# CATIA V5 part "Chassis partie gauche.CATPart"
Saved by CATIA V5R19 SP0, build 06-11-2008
Part number: Bati
Bounding box of the stored display mesh (mm): x 0 to 60, y 0 to 700, z 0 to 900
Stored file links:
  C:\Users\Hicham57\Desktop\Chassis presse\Chassis partie gauche.CATPart
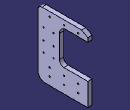
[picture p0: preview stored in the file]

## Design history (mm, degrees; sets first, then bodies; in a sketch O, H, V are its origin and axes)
Body1 (main body)
  Sketch1 on yz-plane, origin (0, 0, 0), H (0, 1, 0), V (0, 0, 1)
    line L1 (101.0295, 0) -> (700, 0)
    point P1 (700, 0)
    line L2 (700, 0) -> (700, 320)
    line L3 (700, 320) -> (365.2402, 320)
    line L4 (300, 385.2402) -> (300, 701.3231)
    line L5 (393.6769, 795) -> (700, 795)
    point P3 (700, 795)
    line L6 (700, 795) -> (700, 850)
    line L7 (700, 850) -> (613.3975, 900)
    line L8 (613.3975, 900) -> (58.246, 900)
    point P6 (0, 900)
    line L9 (0, 841.754) -> (0, 101.0295)
    arc A1 centre (365.2402, 385.2402) radius 65.2402 from (365.2402, 320) to (300, 385.2402) cw
    arc A2 centre (393.6769, 701.3231) radius 93.6769 from (300, 701.3231) to (393.6769, 795) cw
    arc A3 centre (58.246, 841.754) radius 58.246 from (58.246, 900) to (0, 841.754) ccw
    arc A4 centre (101.0295, 101.0295) radius 101.0295 from (101.0295, 0) to (0, 101.0295) cw
    length L2 = 320
    distance L3 L5 = 475
    distance L4 L9 = 300
    length L7 = 100
    angle L5 L7 = 150
    radius A1 = 65.2402
    radius A2 = 93.6769
    distance P6 O = 900
    radius A3 = 58.246
    distance O P1 = 700
    radius A4 = 101.0295
    horizontal: L1 H, L3 H, L5 H, L8 H
    vertical: L2 V, L4 V, L6 V, L9 V
    coincidence: P3 L2, P6 V, L8 P6, L9 P6, L1 O, L9 O
    tangency: A1 L3, A1 L4, A2 L4, A2 L5, A3 L8, A3 L9, A4 L1, A4 L9
  Pad1: profile Sketch1, direction (1, 0, 0), length 60
  Sketch2 on end face of Pad1, origin (60, 0, 0), H (0, 1, 0), V (0, 0, 1)
  Sketch3 on start face of Pad1, origin (0, 0, 0), H (0, -1, 0), V (0, 0, 1)
    line L1 (-655, 855) -> (-25, 855)
    line L2 (-25, 855) -> (-25, 815)
    line L3 (-25, 815) -> (-655, 815)
    line L4 (-655, 815) -> (-655, 855)
    line L5 (-275, 685) -> (-25, 685)
    line L6 (-25, 685) -> (-25, 645)
    line L7 (-25, 645) -> (-275, 645)
    line L8 (-275, 645) -> (-275, 685)
    point P7 (-25, 645)
    point P9 (-275, 525)
    line L9 (-275, 525) -> (-25, 525)
    line L10 (-25, 525) -> (-25, 485)
    line L11 (-25, 485) -> (-275, 485)
    line L12 (-275, 485) -> (-275, 525)
    point P11 (-25, 485)
    line L13 (-275, 380) -> (-25, 380)
    line L14 (-25, 380) -> (-25, 340)
    line L15 (-25, 340) -> (-275, 340)
    line L16 (-275, 340) -> (-275, 380)
    point P17 (-655, 240)
    line L17 (-655, 240) -> (-25, 240)
    line L18 (-25, 240) -> (-25, 200)
    line L19 (-25, 200) -> (-655, 200)
    line L20 (-655, 200) -> (-655, 240)
    point P19 (-25, 200)
    point P21 (-655, 130)
    line L21 (-655, 130) -> (-25, 130)
    line L22 (-25, 130) -> (-25, 90)
    line L23 (-25, 90) -> (-655, 90)
    line L24 (-655, 90) -> (-655, 130)
    point P23 (-25, 90)
    length L1 = 630
    length L2 = 40
    distance L3 H = 815
    length L8 = 40
    distance L11 L9 = 40
    distance L15 L13 = 40
    distance L6 L8 = 250
    length L15 = 250
    distance V L6 = 25
    distance L7 H = 645
    distance L11 H = 485
    distance L14 V = 25
    distance L15 H = 340
    distance L19 H = 200
    length L20 = 40
    length L24 = 40
    distance H L23 = 90
    horizontal: L1 H, L3 H, L5 H, L7 H, L9 H, L11 H, L13 H, L15 H, L17 H, L19 H, L21 H, L23 H
    vertical: L2 V, L4 V, L6 V, L8 V, L10 V, L12 V, L14 V, L16 V, L18 V, L20 V, L22 V, L24 V
    coincidence: P7 L2, P9 L8, P11 L2, P17 L4, P19 L14, P21 L4, P23 L2
  Pocket1: profile Sketch3, direction (1, 0, 0), length 30
  Sketch4 on end face of Pad1, origin (60, 0, 0), H (0, 1, 0), V (0, 0, 1)
    circle A1 centre (165, 835) radius 10
    point P1 (165, 835)
    circle A2 centre (565, 835) radius 10
    point P2 (565, 835)
    circle A3 centre (80, 665) radius 10
    point P3 (80, 665)
    circle A4 centre (220, 665) radius 10
    point P4 (220, 665)
    circle A5 centre (80, 505) radius 10
    point P5 (80, 505)
    circle A6 centre (220, 505) radius 10
    point P6 (220, 505)
    circle A7 centre (80, 360) radius 10
    point P7 (80, 360)
    circle A8 centre (220, 360) radius 10
    point P8 (220, 360)
    circle A9 centre (165, 220) radius 10
    point P9 (165, 220)
    circle A10 centre (365, 220) radius 10
    point P10 (365, 220)
    circle A11 centre (565, 220) radius 10
    point P11 (565, 220)
    circle A12 centre (165, 110) radius 10
    point P12 (165, 110)
    circle A13 centre (365, 110) radius 10
    point P13 (365, 110)
    circle A14 centre (565, 110) radius 10
    point P14 (565, 110)
    circle A15 centre (365, 835) radius 10
    point P15 (365, 835)
    reference projected line E1 (25, 815) -> (25, 855) from edge [end face of Pocket1 | face of Pocket1 from Sketch3.L2]
    reference projected line E2 (655, 815) -> (25, 815) from edge [end face of Pocket1 | face of Pocket1 from Sketch3.L3]
    reference projected line E3 (655, 815) -> (25, 815) from edge [end face of Pocket1 | face of Pocket1 from Sketch3.L3]
    reference projected line E4 (655, 815) -> (25, 815) from edge [end face of Pocket1 | face of Pocket1 from Sketch3.L3]
    reference projected line E5 (25, 200) -> (25, 240) from edge [start face of Pad1 | face of Pocket1 from Sketch3.L18]
    reference projected line E6 (655, 200) -> (25, 200) from edge [end face of Pocket1 | face of Pocket1 from Sketch3.L19]
    reference projected line E7 (655, 200) -> (25, 200) from edge [end face of Pocket1 | face of Pocket1 from Sketch3.L19]
    reference projected line E8 (655, 200) -> (25, 200) from edge [end face of Pocket1 | face of Pocket1 from Sketch3.L19]
    reference projected line E9 (25, 90) -> (25, 130) from edge [end face of Pocket1 | face of Pocket1 from Sketch3.L22]
    reference projected line E10 (655, 90) -> (25, 90) from edge [end face of Pocket1 | face of Pocket1 from Sketch3.L23]
    reference projected line E11 (655, 90) -> (25, 90) from edge [end face of Pocket1 | face of Pocket1 from Sketch3.L23]
    reference projected line E12 (655, 90) -> (25, 90) from edge [end face of Pocket1 | face of Pocket1 from Sketch3.L23]
    reference projected line E13 (25, 645) -> (25, 685) from edge [end face of Pocket1 | face of Pocket1 from Sketch3.L6]
    reference projected line E14 (275, 685) -> (275, 645) from edge [end face of Pocket1 | face of Pocket1 from Sketch3.L8]
    reference projected line E15 (275, 645) -> (25, 645) from edge [end face of Pocket1 | face of Pocket1 from Sketch3.L7]
    reference projected line E16 (25, 485) -> (25, 525) from edge [end face of Pocket1 | face of Pocket1 from Sketch3.L10]
    reference projected line E17 (275, 525) -> (275, 485) from edge [end face of Pocket1 | face of Pocket1 from Sketch3.L12]
    reference projected line E18 (275, 485) -> (25, 485) from edge [end face of Pocket1 | face of Pocket1 from Sketch3.L11]
    reference projected line E19 (25, 340) -> (25, 380) from edge [start face of Pad1 | face of Pocket1 from Sketch3.L14]
    reference projected line E20 (275, 380) -> (275, 340) from edge [end face of Pocket1 | face of Pocket1 from Sketch3.L16]
    reference projected line E21 (275, 340) -> (25, 340) from edge [end face of Pocket1 | face of Pocket1 from Sketch3.L15]
    radius A1 = 10
    radius A15 = 10
    radius A2 = 10
    radius A3 = 10
    radius A4 = 10
    radius A5 = 10
    radius A6 = 10
    radius A7 = 10
    radius A8 = 10
    radius A9 = 10
    radius A10 = 10
    radius A11 = 10
    radius A12 = 10
    radius A13 = 10
    radius A14 = 10
    distance A1 E1 = 150
    distance A1 E2 = 10
    distance A15 E3 = 10
    distance A2 E4 = 10
    distance P15 P1 = 200
    distance P2 P15 = 200
    distance P9 E5 = 140
    distance P9 P10 = 200
    distance P11 P10 = 200
    distance P9 E6 = 20
    distance P10 E7 = 20
    distance P11 E8 = 20
    distance P12 E9 = 140
    distance P12 P13 = 200
    distance P14 P13 = 200
    distance A12 E10 = 10
    distance A13 E11 = 10
    distance A14 E12 = 10
    distance P3 P4 = 140
    distance P3 E13 = 55
    distance P4 E14 = 55
    distance A3 E15 = 10
    distance E16 P5 = 55
    distance P5 P6 = 140
    distance P6 E17 = 55
    distance P6 E18 = 20
    distance P7 E19 = 55
    distance P8 P7 = 140
    distance E20 P8 = 55
    distance P8 E21 = 20
  Pocket2: profile Sketch4, direction (-1, 0, 0), length 60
